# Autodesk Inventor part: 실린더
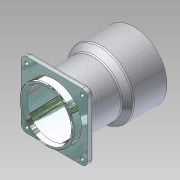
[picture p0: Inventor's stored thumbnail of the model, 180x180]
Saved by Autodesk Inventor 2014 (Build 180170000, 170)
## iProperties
Manager: KYOUNG IL JANG
Company: 한국ATC센터
Created: 2012-10
Part Number: 실린더
Material: Generic
Document SubType Name: 모델링
Density: 1 g/cm^3
Checked By: KYOUNG IL JANG
Vendor: CBT Solutions
Designer: KYOUNG IL JANG
Appearance: _시험_알루미늄 표면거칠기
Author: KYOUNG IL JANG
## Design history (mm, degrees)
revolve "회전1" stored, may be unused: angle "d6" = 90 deg
node "작업 평면1"
sketch "스케치2"
  geometry: L1 (-42.5, 42.5)-(42.5, 42.5); L2 (42.5, 42.5)-(42.5, -42.5); L3 (42.5, -42.5)-(-42.5, -42.5); L4 (-42.5, -42.5)-(-42.5, 42.5); C1 r 35 at (0, 0) reference; 3 further points
  constraints: 8 end point, 2 midpoint, 2 parallel, 2 perpendicular, 1 horizontal, 1 horizontal alignment, 1 vertical alignment
  dimensions: "d8" = 85 distance of L1.end L2.end
extrude "돌출1" join sketch "스케치2" distance "d9" = 8; taper "d10" = 0 deg
fillet "모깎기1" dims "d11" = 7, "d12" = 3
sketch "스케치3"
  geometry: L1 (0, 42.5)-(0, 30); 4 further points
  constraints: 2 end point, 2 vertical alignment, 1 midpoint, 1 point on line, 1 vertical, 2 other
hole "구멍1" sketch "스케치3" diameter "d14" = 4.134; stored, may be unused: countersink angle "d18" = 90 deg, drill point angle "d20" = 118 deg; dims "d15" = 12, "d16" = 4, "d17" = 2, "d19" = 15
sketch "스케치4"
  geometry: C1 r 1.621 at (35.5, -35.5) reference; C2 r 1.621 at (35.5, 35.5) reference; C3 r 1.621 at (-35.5, -35.5) reference; C4 r 1.621 at (-35.5, 35.5) reference; 1 further point
hole "구멍2" sketch "스케치4" diameter "d26" = 4.5; stored, may be unused: countersink angle "d30" = 90 deg, drill point angle "d32" = 118 deg; dims "d27" = 12, "d28" = 8, "d29" = 4.4, "d31" = 15
chamfer "모따기1" distance "d35" = 5; stored, may be unused: second distance "d36" = 2, angle "d37" = 20 deg
chamfer "모따기2" distance "d38" = 1; stored, may be unused: second distance "d39" = 2, angle "d40" = 20 deg
node "솔리드1"
sketch "스케치1"
  geometry: L1 (0, 0)-(0, 112); L2 (30, 0)-(30, 112); L3 (30, 112)-(42.5, 112); L4 (42.5, 112)-(42.5, 69); L5 (42.5, 69)-(35, 61); L6 (35, 61)-(35, 0); L7 (35, 0)-(30, 0)
  constraints: 14 end point, 4 parallel, 2 point on line, 1 perpendicular, 1 vertical
  dimensions: "d0" = 112 distance of L1.start L1.end; "d2" = 85 diameter of L4 L1; "d3" = 70 diameter of L6 L1; "d5" = 60 diameter of L2 L1; "d33" = 43 distance of L3.end L4.end; "d34" = 51 distance from line of L3 L5.end
pattern_circular "원형 패턴1" dims angle "d22" = 360 deg
node "참조1"
node "참조2"
node "참조3"
node "참조4"
other parameters: "KFactor" = 4.4
